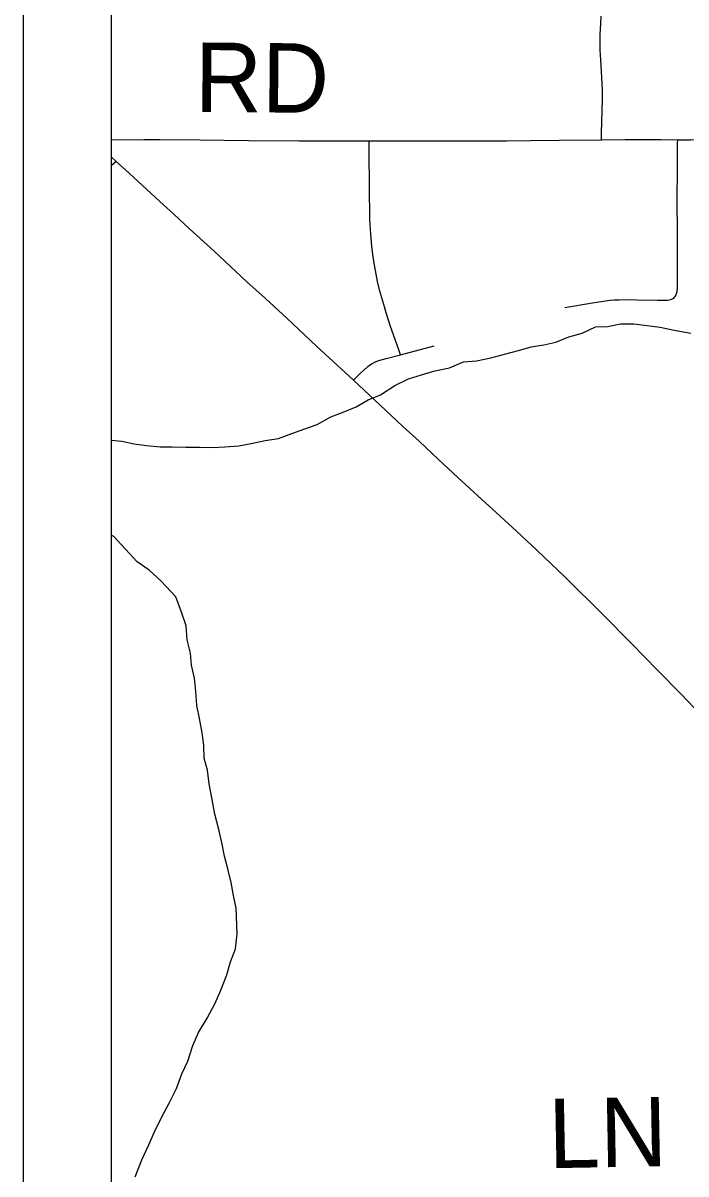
# Model space of a CAD drawing. Extents: x 0 to 34, y 0 to 22.
# Drawn here: x 22.999 to 23.542, y 11.096 to 12.038 of the extents above; entities that cross this region are included whole.
import ezdxf

# ---------------------------------------------------------------- set-up
doc = ezdxf.new("R2010")
doc.units = 0
for name, color, linetype in [('GM_X_Corporation', 7, 'Continuous'), ('GM_X_County_Road_Text', 7, 'Continuous'), ('GM_X_Minor_River', 7, 'Continuous'), ('GM_X_State_Route', 7, 'Continuous'), ('GM_X_Township_Road', 7, 'Continuous'), ('GM_X_Township_Road_Text', 7, 'Continuous'), ('SH_Data', 7, 'Continuous')]:
    doc.layers.add(name, color=color, linetype=linetype)

msp = doc.modelspace()

# ---------------------------------------------------------------- linework, layer by layer
at = {"layer": 'GM_X_Corporation'}
msp.add_lwpolyline([(23.07148, 12.71512), (23.07148, 9.90675), (27.93002, 9.90675)], dxfattribs=at)
at = {"layer": 'GM_X_Minor_River'}
for points in [[(23.07148, 11.69683), (23.08005, 11.69595), (23.09028, 11.69375), (23.10014, 11.69231), (23.1115, 11.69126), (23.12134, 11.69134), (23.13232, 11.69104), (23.14367, 11.69113), (23.15427, 11.69083), (23.16448, 11.69129), (23.17583, 11.69213), (23.18604, 11.69411), (23.19737, 11.69647), (23.20834, 11.69807), (23.21928, 11.70233), (23.22984, 11.7062), (23.24003, 11.70969), (23.25096, 11.71584), (23.26115, 11.71971), (23.27171, 11.72396), (23.28151, 11.72972), (23.29169, 11.73397), (23.30337, 11.74165), (23.31468, 11.74704), (23.32525, 11.75016), (23.3362, 11.75365), (23.34829, 11.75602), (23.35961, 11.76103), (23.37019, 11.76187), (23.38191, 11.76424), (23.39437, 11.76737), (23.40457, 11.7701), (23.41514, 11.77321), (23.42535, 11.77481), (23.43517, 11.77716), (23.44574, 11.78141), (23.45669, 11.78453), (23.46762, 11.78954), (23.47746, 11.79), (23.48804, 11.79198), (23.49902, 11.79206), (23.51, 11.79063), (23.52061, 11.78919), (23.53198, 11.787), (23.54563, 11.78445)], [(23.10246, 11.59034), (23.09257, 11.59708), (23.08302, 11.60763), (23.07348, 11.61779), (23.07148, 11.61897)], [(23.09087, 11.09354), (23.09644, 11.10761), (23.10202, 11.11941), (23.10686, 11.13045), (23.11244, 11.14224), (23.11916, 11.15443), (23.12474, 11.16584), (23.12919, 11.17801), (23.13403, 11.18829), (23.13809, 11.20121), (23.14293, 11.21187), (23.15002, 11.22367), (23.15636, 11.23586), (23.1612, 11.24651), (23.16602, 11.25906), (23.16896, 11.2697), (23.17304, 11.28035), (23.17446, 11.29249), (23.17354, 11.31372), (23.17156, 11.32394), (23.16959, 11.33454), (23.16684, 11.3459), (23.16412, 11.35611), (23.16214, 11.36595), (23.15979, 11.37693), (23.15627, 11.39055), (23.15391, 11.40267), (23.15153, 11.41554), (23.15031, 11.42653), (23.14758, 11.43637), (23.14712, 11.44698), (23.14591, 11.45721), (23.14393, 11.46743), (23.14156, 11.47954), (23.14072, 11.49091), (23.13949, 11.5019), (23.13714, 11.51249), (23.1363, 11.52235), (23.13357, 11.53332), (23.13272, 11.54469), (23.12885, 11.55604), (23.1242, 11.56851), (23.11237, 11.58131), (23.10246, 11.59034)]]:
    msp.add_lwpolyline(points, dxfattribs=at)
at = {"layer": 'GM_X_State_Route'}
msp.add_lwpolyline([(23.07148, 11.92875), (23.07555, 11.92503), (23.08604, 11.91542), (23.11116, 11.89221), (23.12253, 11.8818), (23.13538, 11.86991), (23.15563, 11.85152), (23.18249, 11.82654), (23.19759, 11.81268), (23.21502, 11.79672), (23.23967, 11.77354), (23.2697, 11.74582), (23.28279, 11.73361), (23.2958, 11.72134), (23.31001, 11.70812), (23.32325, 11.69589), (23.33922, 11.68097), (23.35514, 11.66631), (23.37145, 11.65127), (23.38665, 11.63721), (23.40306, 11.62221), (23.41975, 11.60665), (23.44274, 11.58454), (23.4737, 11.55407), (23.49708, 11.53029), (23.51827, 11.50856), (23.53737, 11.48914), (23.54842, 11.47762)], dxfattribs=at)
at = {"layer": 'GM_X_Township_Road'}
for p, q in [((23.07555, 11.92503), (23.07148, 11.92135)), ((23.30807, 11.76673), (23.33569, 11.77413))]:
    msp.add_line(p, q, dxfattribs=at)
for points in [[(23.47246, 11.94279), (23.47263, 11.94839), (23.47342, 11.97568), (23.47342, 11.98012), (23.47334, 11.98376), (23.47315, 11.98855), (23.47192, 12.00836), (23.47169, 12.01211), (23.4715, 12.01632), (23.47144, 12.01873), (23.4714, 12.02198), (23.4714, 12.02439), (23.47145, 12.02631), (23.47157, 12.02921), (23.47196, 12.03755), (23.4722, 12.04396)], [(23.07148, 11.94276), (23.09799, 11.94309), (23.11096, 11.94309), (23.14426, 11.94278), (23.18368, 11.94226), (23.22506, 11.94189), (23.28251, 11.94187)], [(23.28251, 11.94187), (23.31319, 11.94187), (23.37966, 11.94193), (23.39518, 11.94202), (23.41441, 11.94214), (23.43794, 11.9425), (23.47246, 11.94279)], [(23.30807, 11.76673), (23.30635, 11.77169), (23.30002, 11.78983), (23.29641, 11.80103), (23.29432, 11.80787), (23.2912, 11.81881), (23.28935, 11.82668), (23.28815, 11.83265), (23.28664, 11.84168), (23.28557, 11.84874), (23.28473, 11.85553), (23.28411, 11.86203), (23.28382, 11.86573), (23.28331, 11.87348), (23.28306, 11.87794), (23.28298, 11.88019), (23.2829, 11.88382), (23.28274, 11.89858), (23.28252, 11.93824), (23.28251, 11.94187)], [(23.47246, 11.94279), (23.49194, 11.94295), (23.52114, 11.94288), (23.53491, 11.94276)], [(23.53165, 11.81318), (23.53235, 11.81387), (23.53282, 11.81446), (23.5336, 11.81582), (23.53402, 11.81691), (23.53441, 11.81851), (23.53455, 11.8196), (23.53463, 11.82096), (23.53466, 11.82424), (23.53472, 11.83291), (23.53464, 11.86827), (23.53451, 11.89152), (23.53469, 11.92083), (23.53469, 11.92574), (23.53487, 11.93992), (23.53491, 11.94276)], [(23.53491, 11.94276), (23.54562, 11.94283), (23.59098, 11.94305), (23.64664, 11.94346), (23.68346, 11.94362)], [(23.4425, 11.80541), (23.46522, 11.80914), (23.4757, 11.81095), (23.47952, 11.81142), (23.48296, 11.81167), (23.4871, 11.81182), (23.49244, 11.81185), (23.50141, 11.81159)], [(23.50141, 11.81159), (23.51835, 11.81143), (23.52576, 11.81146), (23.52659, 11.81149), (23.5278, 11.8116), (23.52916, 11.8119), (23.52995, 11.81218), (23.53059, 11.81249), (23.53165, 11.81318)], [(23.2697, 11.74582), (23.2752, 11.75148), (23.28126, 11.75699), (23.28274, 11.75817), (23.28484, 11.7596), (23.28646, 11.7605), (23.28809, 11.76122), (23.29038, 11.76201), (23.29642, 11.7637), (23.30807, 11.76673)]]:
    msp.add_lwpolyline(points, dxfattribs=at)
at = {"layer": 'SH_Data'}
msp.add_line((22.99924, 16.77486), (22.99924, 9.77486), dxfattribs=at)

# ---------------------------------------------------------------- texts
at = {"layer": 'GM_X_County_Road_Text'}
msp.add_text('LN', height=0.056818, rotation=1.03168, dxfattribs=at).set_placement((23.4295, 11.10065))
at = {"layer": 'GM_X_Township_Road_Text'}
msp.add_text('RD', height=0.056818, rotation=359.50894, dxfattribs=at).set_placement((23.13964, 11.96565))

doc.saveas('drawing.dxf')
